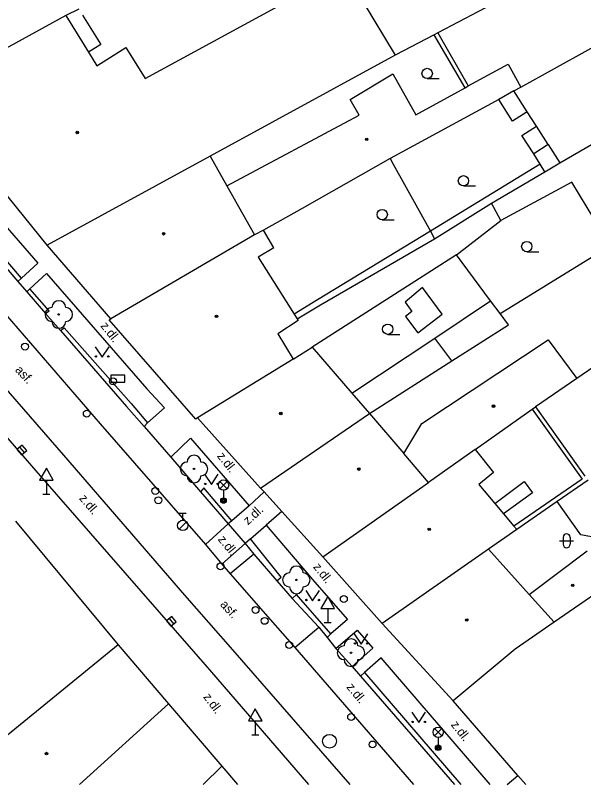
# Model space of a CAD drawing. Extents: x -595546 to -593986, y -1160845 to -1159202.
# Drawn here: x -595306.1 to -595264.9, y -1160843.2 to -1160787.5 of the extents above; entities that cross this region are included whole.
import ezdxf

# ---------------------------------------------------------------- set-up
doc = ezdxf.new("R2010")
doc.units = 0
for name, color, linetype in [('DOP - kresba z DSPS bez souradnic', 7, 'Continuous'), ('DOP - ploty', 7, 'Continuous'), ('DOP - rozhrani ploch obecne', 7, 'Continuous'), ('Level 22', 7, 'Continuous'), ('Level 24', 7, 'Continuous'), ('Level 27', 7, 'Continuous'), ('Level 28', 7, 'Continuous'), ('Level 33', 7, 'Continuous'), ('Level 34', 7, 'Continuous'), ('Level 36', 7, 'Continuous'), ('Level 39', 7, 'Continuous'), ('Specificka linie pasportu komunikaci', 7, 'Continuous'), ('TM - budovy zdene_ betonove - VP', 7, 'Continuous'), ('TM - chodniky - VP', 7, 'Continuous'), ('TM - komunikace - VP', 7, 'Continuous'), ('TM - letecke snimky - pomocna linie', 7, 'Continuous'), ('TM - popis povrchu', 7, 'Continuous'), ('TM - rozhrani mezi zpev. plochami mezi sebou - VP', 7, 'Continuous'), ('TM - rozhrani ploch obecne - VP', 7, 'Continuous')]:
    doc.layers.add(name, color=color, linetype=linetype)

msp = doc.modelspace()

# ---------------------------------------------------------------- linework, layer by layer
at = {"layer": 'DOP - kresba z DSPS bez souradnic'}
for points in [[(-595301.19, -1160787.46), (-595299.86, -1160789.59)], [(-595273.46, -1160792.72), (-595275.7, -1160788.88)], [(-595299.86, -1160789.59), (-595300.76, -1160790.15)], [(-595267.43, -1160796.84), (-595268.49, -1160797.52)], [(-595268.01, -1160798.27), (-595275.98, -1160803.12)], [(-595275.98, -1160803.12), (-595284.17, -1160808.09)], [(-595276.55, -1160807.2), (-595277.8, -1160808.27)], [(-595275.13, -1160809.15), (-595276.55, -1160807.2)], [(-595284.17, -1160808.09), (-595285.86, -1160809.13)], [(-595285.64, -1160809.47), (-595283.95, -1160808.45)], [(-595277.8, -1160808.27), (-595277.33, -1160808.95)], [(-595275.66, -1160810.87), (-595271.61, -1160808.16)], [(-595277.33, -1160808.95), (-595277.77, -1160809.31)], [(-595277.77, -1160809.31), (-595276.88, -1160810.48)], [(-595276.88, -1160810.48), (-595275.13, -1160809.15)], [(-595281.68, -1160814.86), (-595275.66, -1160810.87)], [(-595274.41, -1160812.53), (-595275.66, -1160810.87)], [(-595268.6, -1160816.03), (-595264.97, -1160821.11)], [(-595271.3, -1160822.87), (-595269.18, -1160821.27)], [(-595264.97, -1160821.11), (-595269.93, -1160824.51)], [(-595269.18, -1160821.27), (-595268.57, -1160822.08)], [(-595268.57, -1160822.08), (-595270.67, -1160823.62)]]:
    msp.add_lwpolyline(points, dxfattribs=at)
at = {"layer": 'DOP - ploty'}
msp.add_lwpolyline([(-595270.92, -1160809.08), (-595264.24, -1160804.99)], dxfattribs=at)
at = {"layer": 'DOP - rozhrani ploch obecne'}
for points in [[(-595275.43, -1160788.74), (-595273.23, -1160792.59)], [(-595270.02, -1160795.14), (-595271.02, -1160793.58)], [(-595268.96, -1160794.46), (-595270.02, -1160795.14)], [(-595269.35, -1160796.19), (-595268.28, -1160795.51)], [(-595268.49, -1160797.52), (-595269.35, -1160796.19)], [(-595278.89, -1160797.86), (-595278.67, -1160798.26)], [(-595268.01, -1160798.27), (-595268.49, -1160797.52)], [(-595278.67, -1160798.26), (-595275.98, -1160803.12)], [(-595267.67, -1160798.81), (-595268.01, -1160798.27)], [(-595267.67, -1160798.81), (-595266.59, -1160798.16)], [(-595271.54, -1160801.09), (-595267.67, -1160798.81)], [(-595265.73, -1160799.58), (-595270.87, -1160802.36)], [(-595262.94, -1160804.17), (-595265.73, -1160799.58)], [(-595275.67, -1160803.67), (-595271.54, -1160801.09)], [(-595270.87, -1160802.36), (-595271.54, -1160801.09)], [(-595275.98, -1160803.12), (-595275.67, -1160803.67)], [(-595283.95, -1160808.45), (-595275.67, -1160803.67)], [(-595274.09, -1160804.84), (-595284.54, -1160811.53)], [(-595271.61, -1160808.16), (-595274.09, -1160804.84)], [(-595270.92, -1160809.08), (-595271.61, -1160808.16)], [(-595270.31, -1160809.9), (-595270.92, -1160809.08)], [(-595274.41, -1160812.53), (-595270.31, -1160809.9)], [(-595259.89, -1160810.05), (-595265.36, -1160813.81)], [(-595280.4, -1160816.34), (-595274.41, -1160812.53)], [(-595268.35, -1160815.86), (-595264.77, -1160820.88)], [(-595266.79, -1160822.72), (-595269.72, -1160824.75)]]:
    msp.add_lwpolyline(points, dxfattribs=at)
at = {"layer": 'Level 22'}
for centre in [(-595302.91, -1160809.16), (-595293.11, -1160820.36), (-595285.69, -1160828.4), (-595281.73, -1160833.68)]:
    msp.add_circle(centre, 0.05, dxfattribs=at)
for centre, start, end in [((-595302.91, -1160808.66), 0, 180), ((-595303.41, -1160809.16), 90, 270), ((-595302.41, -1160809.16), 270, 90), ((-595302.91, -1160809.66), 180, 0), ((-595293.11, -1160819.86), 0, 180), ((-595293.61, -1160820.36), 90, 270), ((-595292.61, -1160820.36), 270, 90), ((-595293.11, -1160820.86), 180, 0), ((-595285.69, -1160827.9), 0, 180), ((-595286.19, -1160828.4), 90, 270), ((-595285.19, -1160828.4), 270, 90), ((-595285.69, -1160828.9), 180, 0), ((-595281.73, -1160833.18), 0, 180), ((-595282.23, -1160833.68), 90, 270), ((-595281.23, -1160833.68), 270, 90), ((-595281.73, -1160834.18), 180, 0)]:
    msp.add_arc(centre, 0.5, start, end, dxfattribs=at)
at = {"layer": 'Level 24'}
msp.add_lwpolyline([(-595299.128, -1160814.069), (-595298.128, -1160814.069), (-595298.128, -1160813.569), (-595299.128, -1160813.569)], close=True, dxfattribs=at)
at = {"layer": 'Level 27'}
for p, q in [((-595305.751, -1160818.789), (-595305.429, -1160819.171)), ((-595294.907, -1160831.206), (-595294.593, -1160831.594))]:
    msp.add_line(p, q, dxfattribs=at)
for points in [[(-595305.942, -1160818.949), (-595305.621, -1160819.332), (-595305.238, -1160819.011), (-595305.559, -1160818.628)], [(-595295.102, -1160831.363), (-595294.787, -1160831.752), (-595294.398, -1160831.437), (-595294.713, -1160831.048)]]:
    msp.add_lwpolyline(points, close=True, dxfattribs=at)
msp.add_circle((-595283.29, -1160840.1), 0.5, dxfattribs=at)
at = {"layer": 'Level 28'}
for p, q in [((-595294.18, -1160823.575), (-595293.68, -1160823.575)), ((-595293.93, -1160824.075), (-595293.93, -1160823.575)), ((-595294.188, -1160824.722), (-595293.658, -1160824.192))]:
    msp.add_line(p, q, dxfattribs=at)
for centre, radius in [((-595305.36, -1160811.49), 0.25), ((-595298.98, -1160814), 0.25), ((-595300.88, -1160816.35), 0.25), ((-595295.92, -1160821.95), 0.25), ((-595295.69, -1160822.63), 0.25), ((-595293.93, -1160824.45), 0.375), ((-595291.19, -1160827.42), 0.25), ((-595282.25, -1160829.79), 0.25), ((-595288.65, -1160830.58), 0.25), ((-595287.99, -1160831.37), 0.25), ((-595286.21, -1160833.12), 0.25), ((-595281.72, -1160838.34), 0.25), ((-595280.17, -1160840.33), 0.25)]:
    msp.add_circle(centre, radius, dxfattribs=at)
at = {"layer": 'Level 33'}
for p, q in [((-595291.235, -1160821.79), (-595290.705, -1160821.26)), ((-595291.235, -1160821.26), (-595290.705, -1160821.79)), ((-595290.97, -1160821.9), (-595290.97, -1160822.65)), ((-595275.675, -1160839.71), (-595275.145, -1160839.18)), ((-595275.675, -1160839.18), (-595275.145, -1160839.71)), ((-595275.41, -1160839.82), (-595275.41, -1160840.57))]:
    msp.add_line(p, q, dxfattribs=at)
for centre, radius in [((-595290.97, -1160821.525), 0.375), ((-595290.97, -1160822.65), 0.2), ((-595290.97, -1160822.65), 0.145), ((-595290.97, -1160822.65), 0.0876), ((-595275.41, -1160839.445), 0.375), ((-595275.41, -1160840.57), 0.2), ((-595275.41, -1160840.57), 0.145), ((-595275.41, -1160840.57), 0.0876)]:
    msp.add_circle(centre, radius, dxfattribs=at)
at = {"layer": 'Level 34'}
for p, q in [((-595303.81, -1160821.172), (-595303.81, -1160822.19)), ((-595304.06, -1160822.19), (-595303.56, -1160822.19)), ((-595283.42, -1160830.472), (-595283.42, -1160831.49)), ((-595283.67, -1160831.49), (-595283.17, -1160831.49)), ((-595288.67, -1160838.622), (-595288.67, -1160839.64)), ((-595288.92, -1160839.64), (-595288.42, -1160839.64))]:
    msp.add_line(p, q, dxfattribs=at)
for points in [[(-595304.31, -1160821.172), (-595303.31, -1160821.172), (-595303.81, -1160820.306)], [(-595283.92, -1160830.472), (-595282.92, -1160830.472), (-595283.42, -1160829.606)], [(-595289.17, -1160838.622), (-595288.17, -1160838.622), (-595288.67, -1160837.756)]]:
    msp.add_lwpolyline(points, close=True, dxfattribs=at)
at = {"layer": 'Level 36'}
for p, q in [((-595276.21, -1160792.065), (-595275.335, -1160792.065)), ((-595273.58, -1160799.845), (-595272.705, -1160799.845)), ((-595279.47, -1160802.295), (-595278.595, -1160802.295)), ((-595268.99, -1160804.615), (-595268.115, -1160804.615)), ((-595279.07, -1160810.605), (-595278.195, -1160810.605)), ((-595266.606, -1160825.566), (-595265.606, -1160825.566)), ((-595266.356, -1160825.316), (-595266.356, -1160825.816)), ((-595265.856, -1160825.316), (-595265.856, -1160825.816))]:
    msp.add_line(p, q, dxfattribs=at)
for points in [[(-595300.27, -1160811.5), (-595299.77, -1160812.25), (-595299.27, -1160811.5)], [(-595292.35, -1160820.74), (-595291.85, -1160821.49), (-595291.35, -1160820.74)], [(-595285.01, -1160829.16), (-595284.51, -1160829.91), (-595284.01, -1160829.16)], [(-595281.5, -1160832.31), (-595281, -1160833.06), (-595280.5, -1160832.31)], [(-595277.32, -1160838), (-595276.82, -1160838.75), (-595276.32, -1160838)]]:
    msp.add_lwpolyline(points, dxfattribs=at)
for centre, radius in [((-595276.21, -1160791.69), 0.375), ((-595273.58, -1160799.47), 0.375), ((-595279.47, -1160801.92), 0.375), ((-595268.99, -1160804.24), 0.375), ((-595279.07, -1160810.23), 0.375), ((-595300.22, -1160812.2), 0.05), ((-595299.321, -1160812.2), 0.05), ((-595292.3, -1160821.44), 0.05), ((-595291.401, -1160821.44), 0.05), ((-595284.96, -1160829.86), 0.05), ((-595284.061, -1160829.86), 0.05), ((-595281.45, -1160833.01), 0.05), ((-595280.551, -1160833.01), 0.05), ((-595277.27, -1160838.7), 0.05), ((-595276.371, -1160838.7), 0.05)]:
    msp.add_circle(centre, radius, dxfattribs=at)
for centre, start, end in [((-595266.106, -1160825.316), 0, 180), ((-595266.106, -1160825.816), 180, 0)]:
    msp.add_arc(centre, 0.25, start, end, dxfattribs=at)
at = {"layer": 'Level 39'}
for centre, radius in [((-595301.57, -1160795.97), 0.09), ((-595301.57, -1160795.97), 0.0398), ((-595280.59, -1160796.47), 0.09), ((-595280.59, -1160796.47), 0.0398), ((-595295.31, -1160803.31), 0.09), ((-595295.31, -1160803.31), 0.0398), ((-595291.48, -1160809.29), 0.09), ((-595291.48, -1160809.29), 0.0398), ((-595271.4, -1160815.81), 0.09), ((-595286.82, -1160816.34), 0.09), ((-595286.82, -1160816.34), 0.0398), ((-595271.4, -1160815.81), 0.0398), ((-595281.16, -1160820.37), 0.09), ((-595281.16, -1160820.37), 0.0398), ((-595276.06, -1160824.74), 0.09), ((-595276.06, -1160824.74), 0.0398), ((-595265.66, -1160828.8), 0.09), ((-595265.66, -1160828.8), 0.0398), ((-595273.34, -1160831.31), 0.09), ((-595273.34, -1160831.31), 0.0398), ((-595303.8, -1160840.99), 0.09), ((-595303.8, -1160840.99), 0.0398)]:
    msp.add_circle(centre, radius, dxfattribs=at)
at = {"layer": 'Specificka linie pasportu komunikaci'}
msp.add_lwpolyline([(-595289.4, -1160825.77), (-595291.09, -1160827.25)], dxfattribs=at)
at = {"layer": 'TM - budovy zdene_ betonove - VP'}
for points in [[(-595296.65, -1160792.06), (-595282.24, -1160784.2)], [(-595269.55, -1160785.63), (-595275.43, -1160788.74)], [(-595280.92, -1160786.41), (-595278.52, -1160790.37)], [(-595301.46, -1160787.02), (-595302.4, -1160787.5)], [(-595302.4, -1160787.5), (-595312.66, -1160793.12)], [(-595302.4, -1160787.5), (-595300.76, -1160790.15)], [(-595275.7, -1160788.88), (-595278.52, -1160790.37)], [(-595275.43, -1160788.74), (-595275.7, -1160788.88)], [(-595269.43, -1160792.69), (-595262.11, -1160788.62)], [(-595300.15, -1160791.13), (-595298.04, -1160789.82)], [(-595298.04, -1160789.82), (-595296.65, -1160792.06)], [(-595300.76, -1160790.15), (-595300.15, -1160791.13)], [(-595278.52, -1160790.37), (-595291.95, -1160797.69)], [(-595273.23, -1160792.59), (-595270.35, -1160791.02)], [(-595270.35, -1160791.02), (-595269.43, -1160792.69)], [(-595281.78, -1160793.58), (-595278.69, -1160791.71)], [(-595278.69, -1160791.71), (-595277.04, -1160794.68)], [(-595277.04, -1160794.68), (-595273.46, -1160792.72)], [(-595273.46, -1160792.72), (-595273.23, -1160792.59)], [(-595269.92, -1160792.96), (-595269.43, -1160792.69)], [(-595266.59, -1160798.16), (-595256.96, -1160792.58)], [(-595303.75, -1160804.13), (-595312.66, -1160793.12)], [(-595269.92, -1160792.96), (-595271.02, -1160793.58)], [(-595268.96, -1160794.46), (-595269.92, -1160792.96)], [(-595281.15, -1160794.72), (-595281.78, -1160793.58)], [(-595271.02, -1160793.58), (-595278.89, -1160797.86)], [(-595268.28, -1160795.51), (-595268.96, -1160794.46)], [(-595290.73, -1160799.84), (-595281.15, -1160794.72)], [(-595267.43, -1160796.84), (-595268.28, -1160795.51)], [(-595267.43, -1160796.84), (-595266.59, -1160798.16)], [(-595291.95, -1160797.69), (-595303.75, -1160804.13)], [(-595291.95, -1160797.69), (-595290.73, -1160799.84)], [(-595278.89, -1160797.86), (-595285.28, -1160801.49)], [(-595290.73, -1160799.84), (-595288.72, -1160803.39)], [(-595285.28, -1160801.49), (-595288.08, -1160803.04)], [(-595288.72, -1160803.39), (-595299.14, -1160809.48)], [(-595288.08, -1160803.04), (-595288.72, -1160803.39)], [(-595287.32, -1160804.34), (-595288.08, -1160803.04)], [(-595299.14, -1160809.48), (-595303.75, -1160804.13)], [(-595287.32, -1160804.34), (-595288.47, -1160805)], [(-595288.47, -1160805), (-595285.86, -1160809.13)], [(-595299.27, -1160809.56), (-595299.14, -1160809.48)], [(-595292.98, -1160816.74), (-595299.27, -1160809.56)], [(-595285.56, -1160809.6), (-595287.04, -1160810.56)], [(-595285.86, -1160809.13), (-595285.64, -1160809.47)], [(-595285.64, -1160809.47), (-595285.56, -1160809.6)], [(-595287.04, -1160810.56), (-595285.92, -1160812.39)], [(-595276.59, -1160817.07), (-595267.44, -1160811)], [(-595267.44, -1160811), (-595265.36, -1160813.81)], [(-595285.92, -1160812.39), (-595284.54, -1160811.53)], [(-595284.54, -1160811.53), (-595281.68, -1160814.86)], [(-595285.92, -1160812.39), (-595292.85, -1160816.66)], [(-595265.36, -1160813.81), (-595268.35, -1160815.86)], [(-595281.68, -1160814.86), (-595280.4, -1160816.34)], [(-595272.73, -1160818.95), (-595268.6, -1160816.03)], [(-595268.6, -1160816.03), (-595268.35, -1160815.86)], [(-595292.85, -1160816.66), (-595292.98, -1160816.74)], [(-595288.28, -1160821.74), (-595292.85, -1160816.66)], [(-595288.28, -1160821.74), (-595280.4, -1160816.34)], [(-595280.4, -1160816.34), (-595277.91, -1160819.24)], [(-595277.91, -1160819.24), (-595276.59, -1160817.07)], [(-595272.73, -1160818.95), (-595276.11, -1160821.33)], [(-595272.73, -1160818.95), (-595271.4, -1160820.62)], [(-595276.11, -1160821.33), (-595277.91, -1160819.24)], [(-595271.4, -1160820.62), (-595272.46, -1160821.49)], [(-595283.77, -1160826.73), (-595276.11, -1160821.33)], [(-595264.55, -1160821.18), (-595266.79, -1160822.72)], [(-595288.03, -1160822.02), (-595288.28, -1160821.74)], [(-595272.46, -1160821.49), (-595271.3, -1160822.87)], [(-595286.75, -1160823.44), (-595288.03, -1160822.02)], [(-595271.3, -1160822.87), (-595270.67, -1160823.62)], [(-595265.07, -1160825.14), (-595266.79, -1160822.72)], [(-595283.77, -1160826.73), (-595286.75, -1160823.44)], [(-595270.67, -1160823.62), (-595269.93, -1160824.51)], [(-595306.06, -1160824.15), (-595298.6, -1160833.1)], [(-595269.93, -1160824.51), (-595269.72, -1160824.75)], [(-595269.72, -1160824.75), (-595271.77, -1160826.18)], [(-595263.91, -1160825.34), (-595265.07, -1160825.14)], [(-595271.77, -1160826.18), (-595279.47, -1160831.56)], [(-595271.77, -1160826.18), (-595268.82, -1160829.45)], [(-595268.82, -1160829.45), (-595264.62, -1160826.29)], [(-595279.47, -1160831.56), (-595283.77, -1160826.73)], [(-595261.82, -1160827.88), (-595267.01, -1160831.46)], [(-595268.82, -1160829.45), (-595267.01, -1160831.46)], [(-595274.33, -1160837.17), (-595279.47, -1160831.56)], [(-595267.01, -1160831.46), (-595269.84, -1160833.42)], [(-595298.6, -1160833.1), (-595308.5, -1160841.15)], [(-595298.6, -1160833.1), (-595294.95, -1160837.38)], [(-595269.84, -1160833.42), (-595274.33, -1160837.17)], [(-595294.95, -1160837.38), (-595301.422, -1160843.241)], [(-595294.95, -1160837.38), (-595291.09, -1160841.91)], [(-595269.63, -1160842.59), (-595274.33, -1160837.17)], [(-595291.09, -1160841.91), (-595292.449, -1160843.241)], [(-595291.09, -1160841.91), (-595289.955, -1160843.241)], [(-595269.059, -1160843.241), (-595269.63, -1160842.59)]]:
    msp.add_lwpolyline(points, dxfattribs=at)
at = {"layer": 'TM - chodniky - VP'}
for points in [[(-595315.49, -1160795.15), (-595314.28, -1160794.09), (-595306.81, -1160802.72), (-595304.44, -1160805.45), (-595305.61, -1160806.53)], [(-595305, -1160807.3), (-595303.79, -1160806.2), (-595296.54, -1160814.55), (-595295.25, -1160815.94), (-595296.48, -1160817.02)], [(-595305.61, -1160806.53), (-595305.87, -1160806.77)], [(-595305, -1160807.3), (-595305.22, -1160807.52)], [(-595296.48, -1160817.02), (-595296.73, -1160817.29)], [(-595294.79, -1160819.51), (-595293.36, -1160818.13), (-595289.12, -1160823.03)], [(-595289.12, -1160823.03), (-595290.36, -1160824.11)], [(-595290.36, -1160824.11), (-595290.63, -1160824.34)], [(-595289.02, -1160825.43), (-595287.88, -1160824.43)], [(-595287.88, -1160824.43), (-595284.38, -1160828.54), (-595281.99, -1160831.28), (-595283.2, -1160832.3)], [(-595289.02, -1160825.43), (-595289.4, -1160825.77)], [(-595283.2, -1160832.3), (-595283.47, -1160832.57)], [(-595282.82, -1160833.38), (-595281.29, -1160832.04), (-595280.16, -1160833.35), (-595281.65, -1160834.68)], [(-595271.645, -1160843.241), (-595279.55, -1160834.05), (-595280.75, -1160835.12)], [(-595280.75, -1160835.12), (-595281.05, -1160835.38)]]:
    msp.add_lwpolyline(points, dxfattribs=at)
at = {"layer": 'TM - komunikace - VP'}
for points in [[(-595331.79, -1160789.12), (-595324.24, -1160797.83), (-595314.47, -1160809.08), (-595304.26, -1160820.86), (-595291.98, -1160834.93), (-595284.804, -1160843.241)], [(-595315.75, -1160795.4), (-595308.31, -1160803.94), (-595305.87, -1160806.77)], [(-595305.87, -1160806.77), (-595305.22, -1160807.52)], [(-595305.22, -1160807.52), (-595303.87, -1160809.09)], [(-595303.87, -1160809.09), (-595302.78, -1160810.32)], [(-595302.78, -1160810.32), (-595298, -1160815.84), (-595296.73, -1160817.29)], [(-595296.73, -1160817.29), (-595294.79, -1160819.51)], [(-595294.79, -1160819.51), (-595292.63, -1160822.02)], [(-595292.63, -1160822.02), (-595290.63, -1160824.34)], [(-595290.63, -1160824.34), (-595289.4, -1160825.77)], [(-595289.4, -1160825.77), (-595288.78, -1160826.54)], [(-595288.78, -1160826.54), (-595287.1, -1160828.48)], [(-595287.1, -1160828.48), (-595285.99, -1160829.76)], [(-595285.99, -1160829.76), (-595284.07, -1160831.82)], [(-595284.07, -1160831.82), (-595283.47, -1160832.57)], [(-595283.47, -1160832.57), (-595282.82, -1160833.38)], [(-595282.82, -1160833.38), (-595281.65, -1160834.68)], [(-595281.65, -1160834.68), (-595281.05, -1160835.38)], [(-595281.05, -1160835.38), (-595274.227, -1160843.241)]]:
    msp.add_lwpolyline(points, dxfattribs=at)
at = {"layer": 'TM - letecke snimky - pomocna linie'}
msp.add_lwpolyline([(-595274.09, -1160804.84), (-595270.87, -1160802.36)], dxfattribs=at)
at = {"layer": 'TM - rozhrani mezi zpev. plochami mezi sebou - VP'}
for points in [[(-595330.14, -1160787.59), (-595322.57, -1160796.32), (-595312.74, -1160807.68), (-595302.57, -1160819.37), (-595293.79, -1160829.51), (-595290.31, -1160833.46), (-595281.815, -1160843.241)], [(-595323.53, -1160789.84), (-595319.8, -1160794.2), (-595310.03, -1160805.39), (-595299.91, -1160817.08), (-595292.28, -1160825.84)], [(-595290.63, -1160824.34), (-595292.28, -1160825.84)], [(-595292.28, -1160825.84), (-595291.09, -1160827.25)], [(-595288.78, -1160826.54), (-595290.5, -1160827.95)], [(-595291.09, -1160827.25), (-595290.5, -1160827.95)], [(-595290.5, -1160827.95), (-595287.59, -1160831.27), (-595285.8, -1160833.31)], [(-595285.8, -1160833.31), (-595284.07, -1160831.82)], [(-595285.8, -1160833.31), (-595277.195, -1160843.241)], [(-595270.411, -1160843.241), (-595269.63, -1160842.59)]]:
    msp.add_lwpolyline(points, dxfattribs=at)
at = {"layer": 'TM - rozhrani ploch obecne - VP'}
for points in [[(-595305.61, -1160806.53), (-595308.03, -1160803.72), (-595315.49, -1160795.15)], [(-595303.87, -1160809.09), (-595303.6, -1160808.89), (-595305, -1160807.3)], [(-595302.78, -1160810.32), (-595302.52, -1160810.13), (-595297.67, -1160815.62), (-595296.48, -1160817.02)], [(-595290.36, -1160824.11), (-595292.39, -1160821.73), (-595292.63, -1160822.02)], [(-595289.12, -1160823.03), (-595288.03, -1160822.02)], [(-595286.75, -1160823.44), (-595287.88, -1160824.43)], [(-595287.1, -1160828.48), (-595286.79, -1160828.2), (-595289.02, -1160825.43)], [(-595283.2, -1160832.3), (-595285.68, -1160829.47), (-595285.99, -1160829.76)], [(-595280.75, -1160835.12), (-595273.76, -1160843.241)]]:
    msp.add_lwpolyline(points, dxfattribs=at)

# ---------------------------------------------------------------- texts
at = {"layer": 'TM - popis povrchu'}
for s, rotation, p in [('z.dl.', 308.14, (-595299.92, -1160810)), ('asf.', 312.64, (-595306.12, -1160813.22)), ('z.dl.', 308.14, (-595291.47, -1160819.44)), ('z.dl.', 310.22, (-595301.47, -1160822.51)), ('z.dl.', 42.12, (-595289.2, -1160824.45)), ('z.dl.', 309.13, (-595291.41, -1160825.48)), ('z.dl.', 308.14, (-595284.51, -1160827.47)), ('asf.', 312.64, (-595291.26, -1160830.22)), ('z.dl.', 309.13, (-595282.09, -1160836.19)), ('z.dl.', 306.31, (-595292.47, -1160836.89)), ('z.dl.', 308.14, (-595274.52, -1160838.91))]:
    msp.add_text(s, height=0.65, rotation=rotation, dxfattribs=at).set_placement(p)

doc.saveas('drawing.dxf')
